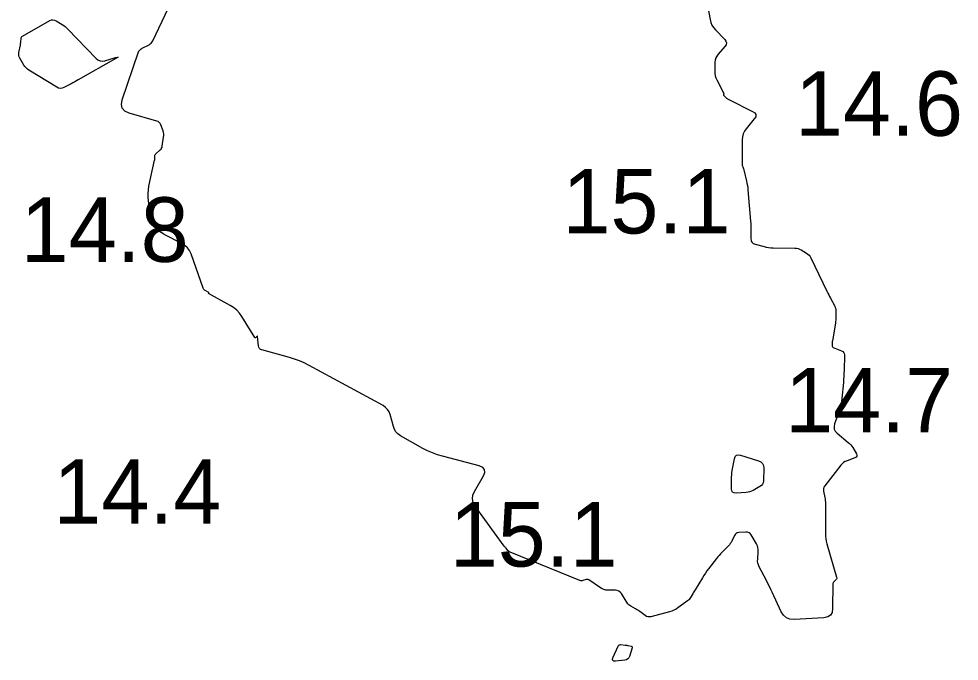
# Model space of a CAD drawing. Extents: x 1023796 to 1112670, y 656573 to 837340.
# Drawn here: x 1101305.4 to 1101378.2, y 688126.7 to 688176.5 of the extents above; entities that cross this region are included whole.
import ezdxf

# ---------------------------------------------------------------- set-up
doc = ezdxf.new("R2010")
doc.units = 0
doc.layers.add('V-CHAN-CONT-15FT', color=7, linetype='Continuous')
doc.layers.add('V-TOPO-SOUN', color=7, linetype='Continuous')

msp = doc.modelspace()

# ---------------------------------------------------------------- linework, layer by layer
at = {"layer": 'V-CHAN-CONT-15FT'}
msp.add_lwpolyline([(1101358.479, 688178.778), (1101358.905, 688176.459), (1101358.963, 688176.235), (1101359.051, 688176.027), (1101359.169, 688175.834), (1101359.318, 688175.657), (1101360.037, 688174.914), (1101360.137, 688174.777), (1101360.172, 688174.638), (1101360.143, 688174.497), (1101360.049, 688174.356), (1101359.524, 688173.764), (1101359.421, 688173.627), (1101359.347, 688173.479), (1101359.3, 688173.319), (1101359.282, 688173.149), (1101359.266, 688172.445), (1101359.272, 688172.271), (1101359.3, 688172.103), (1101359.349, 688171.939), (1101359.42, 688171.781), (1101359.946, 688170.768), (1101359.954, 688170.751), (1101359.959, 688170.733), (1101359.961, 688170.714), (1101359.96, 688170.695), (1101359.953, 688170.618), (1101359.953, 688170.6), (1101359.957, 688170.583), (1101359.965, 688170.568), (1101359.977, 688170.554), (1101360.179, 688170.365), (1101360.218, 688170.33), (1101360.26, 688170.299), (1101360.304, 688170.271), (1101360.35, 688170.247), (1101362.202, 688169.338), (1101362.375, 688169.22), (1101362.454, 688169.082), (1101362.439, 688168.923), (1101362.329, 688168.745), (1101361.704, 688167.991), (1101361.567, 688167.795), (1101361.469, 688167.585), (1101361.411, 688167.362), (1101361.391, 688167.124), (1101361.391, 688165.23), (1101361.392, 688165.202), (1101361.396, 688165.175), (1101361.402, 688165.148), (1101361.411, 688165.122), (1101361.451, 688165.018), (1101361.461, 688164.992), (1101361.47, 688164.966), (1101361.478, 688164.939), (1101361.485, 688164.912), (1101361.726, 688163.937), (1101361.765, 688163.765), (1101361.797, 688163.592), (1101361.823, 688163.418), (1101361.841, 688163.242), (1101362.047, 688160.825), (1101362.06, 688160.656), (1101362.068, 688160.487), (1101362.072, 688160.317), (1101362.073, 688160.148), (1101362.065, 688159.47), (1101362.084, 688159.316), (1101362.144, 688159.194), (1101362.246, 688159.103), (1101362.389, 688159.043), (1101363.089, 688158.855), (1101363.261, 688158.814), (1101363.434, 688158.785), (1101363.609, 688158.766), (1101363.785, 688158.758), (1101365.482, 688158.734), (1101365.606, 688158.724), (1101365.726, 688158.698), (1101365.841, 688158.657), (1101365.951, 688158.599), (1101366.384, 688158.338), (1101366.485, 688158.266), (1101366.573, 688158.183), (1101366.648, 688158.087), (1101366.71, 688157.98), (1101367.96, 688155.391), (1101368.027, 688155.254), (1101368.095, 688155.117), (1101368.165, 688154.981), (1101368.235, 688154.846), (1101368.559, 688154.233), (1101368.604, 688154.133), (1101368.636, 688154.03), (1101368.655, 688153.923), (1101368.66, 688153.813), (1101368.653, 688153.368), (1101368.649, 688153.257), (1101368.641, 688153.146), (1101368.629, 688153.036), (1101368.612, 688152.926), (1101368.379, 688151.541), (1101368.373, 688151.495), (1101368.368, 688151.449), (1101368.365, 688151.403), (1101368.364, 688151.356), (1101368.364, 688151.171), (1101368.369, 688151.128), (1101368.385, 688151.092), (1101368.412, 688151.063), (1101368.449, 688151.041), (1101369.091, 688150.769), (1101369.197, 688150.707), (1101369.271, 688150.626), (1101369.314, 688150.524), (1101369.326, 688150.403), (1101369.289, 688149.262), (1101369.28, 688149.028), (1101369.267, 688148.794), (1101369.25, 688148.561), (1101369.23, 688148.328), (1101369.113, 688147.066), (1101369.082, 688146.818), (1101369.036, 688146.573), (1101368.975, 688146.331), (1101368.899, 688146.092), (1101368.551, 688145.105), (1101368.506, 688144.897), (1101368.525, 688144.707), (1101368.607, 688144.534), (1101368.752, 688144.379), (1101369.604, 688143.676), (1101369.705, 688143.584), (1101369.798, 688143.485), (1101369.881, 688143.379), (1101369.956, 688143.265), (1101370.239, 688142.793), (1101370.284, 688142.685), (1101370.28, 688142.594), (1101370.226, 688142.52), (1101370.121, 688142.465), (1101369.514, 688142.248), (1101369.376, 688142.188), (1101369.251, 688142.111), (1101369.138, 688142.016), (1101369.038, 688141.904), (1101367.792, 688140.305), (1101367.73, 688140.207), (1101367.693, 688140.103), (1101367.681, 688139.994), (1101367.694, 688139.879), (1101367.794, 688139.407), (1101367.816, 688139.288), (1101367.832, 688139.169), (1101367.842, 688139.05), (1101367.847, 688138.929), (1101367.856, 688138.158), (1101367.858, 688137.989), (1101367.859, 688137.821), (1101367.858, 688137.652), (1101367.857, 688137.483), (1101367.847, 688136.607), (1101367.853, 688136.405), (1101367.873, 688136.206), (1101367.907, 688136.009), (1101367.956, 688135.813), (1101368.71, 688133.225), (1101368.719, 688133.173), (1101368.714, 688133.123), (1101368.695, 688133.077), (1101368.661, 688133.035), (1101368.5, 688132.874), (1101368.465, 688132.831), (1101368.44, 688132.785), (1101368.424, 688132.734), (1101368.419, 688132.679), (1101368.401, 688130.787), (1101368.356, 688130.492), (1101368.229, 688130.276), (1101368.019, 688130.138), (1101367.727, 688130.078), (1101365.427, 688129.939), (1101365.094, 688129.961), (1101364.813, 688130.07), (1101364.584, 688130.266), (1101364.408, 688130.549), (1101363.716, 688132.051), (1101363.609, 688132.28), (1101363.499, 688132.507), (1101363.386, 688132.734), (1101363.271, 688132.958), (1101362.712, 688134.031), (1101362.651, 688134.17), (1101362.611, 688134.312), (1101362.592, 688134.459), (1101362.593, 688134.611), (1101362.638, 688135.224), (1101362.638, 688135.375), (1101362.616, 688135.52), (1101362.572, 688135.661), (1101362.505, 688135.796), (1101362.089, 688136.502), (1101362.013, 688136.602), (1101361.921, 688136.67), (1101361.813, 688136.708), (1101361.688, 688136.715), (1101361.125, 688136.679), (1101361.016, 688136.659), (1101360.923, 688136.615), (1101360.848, 688136.545), (1101360.789, 688136.452), (1101360.588, 688136.027), (1101360.533, 688135.923), (1101360.471, 688135.826), (1101360.401, 688135.733), (1101360.322, 688135.647), (1101359.824, 688135.143), (1101359.715, 688135.029), (1101359.61, 688134.913), (1101359.508, 688134.793), (1101359.41, 688134.671), (1101358.795, 688133.88), (1101358.667, 688133.71), (1101358.544, 688133.537), (1101358.426, 688133.361), (1101358.313, 688133.181), (1101357.74, 688132.24), (1101357.695, 688132.165), (1101357.65, 688132.091), (1101357.606, 688132.016), (1101357.561, 688131.941), (1101357.384, 688131.641), (1101357.337, 688131.569), (1101357.283, 688131.503), (1101357.223, 688131.442), (1101357.156, 688131.387), (1101356.417, 688130.839), (1101356.267, 688130.738), (1101356.109, 688130.653), (1101355.944, 688130.584), (1101355.771, 688130.532), (1101354.313, 688130.161), (1101354.198, 688130.144), (1101354.089, 688130.152), (1101353.984, 688130.186), (1101353.885, 688130.246), (1101353.466, 688130.557), (1101353.383, 688130.616), (1101353.299, 688130.672), (1101353.212, 688130.726), (1101353.124, 688130.776), (1101352.766, 688130.972), (1101352.681, 688131.026), (1101352.605, 688131.089), (1101352.538, 688131.161), (1101352.479, 688131.243), (1101352.034, 688131.957), (1101351.945, 688132.068), (1101351.839, 688132.148), (1101351.716, 688132.196), (1101351.574, 688132.212), (1101350.974, 688132.213), (1101350.827, 688132.224), (1101350.687, 688132.256), (1101350.554, 688132.31), (1101350.427, 688132.385), (1101349.517, 688133.013), (1101349.465, 688133.041), (1101349.41, 688133.056), (1101349.354, 688133.056), (1101349.296, 688133.041), (1101349.06, 688132.956), (1101349.001, 688132.941), (1101348.943, 688132.936), (1101348.884, 688132.943), (1101348.826, 688132.961), (1101343.426, 688135.172), (1101343.376, 688135.196), (1101343.33, 688135.225), (1101343.287, 688135.258), (1101343.248, 688135.297), (1101343.099, 688135.462), (1101343.062, 688135.504), (1101343.026, 688135.547), (1101342.992, 688135.59), (1101342.958, 688135.635), (1101340.712, 688138.719), (1101340.556, 688139.002), (1101340.494, 688139.289), (1101340.525, 688139.581), (1101340.651, 688139.878), (1101341.343, 688141.076), (1101341.453, 688141.349), (1101341.435, 688141.569), (1101341.291, 688141.736), (1101341.02, 688141.851), (1101338.18, 688142.593), (1101337.784, 688142.71), (1101337.399, 688142.852), (1101337.024, 688143.018), (1101336.659, 688143.209), (1101334.918, 688144.191), (1101334.726, 688144.324), (1101334.572, 688144.485), (1101334.455, 688144.675), (1101334.374, 688144.893), (1101334.126, 688145.825), (1101334.046, 688146.043), (1101333.928, 688146.231), (1101333.772, 688146.391), (1101333.579, 688146.521), (1101327.836, 688149.645), (1101327.47, 688149.831), (1101327.096, 688149.994), (1101326.712, 688150.136), (1101326.319, 688150.255), (1101324.187, 688150.836), (1101324.076, 688150.882), (1101323.994, 688150.952), (1101323.941, 688151.045), (1101323.916, 688151.162), (1101323.856, 688151.87), (1101323.851, 688151.895), (1101323.841, 688151.907), (1101323.826, 688151.904), (1101323.805, 688151.888), (1101323.715, 688151.798), (1101323.693, 688151.781), (1101323.672, 688151.777), (1101323.653, 688151.786), (1101323.635, 688151.807), (1101322.632, 688153.43), (1101322.449, 688153.69), (1101322.236, 688153.919), (1101321.996, 688154.119), (1101321.727, 688154.289), (1101320.045, 688155.208), (1101320.038, 688155.213), (1101320.035, 688155.219), (1101320.036, 688155.226), (1101320.042, 688155.233), (1101320.071, 688155.262), (1101320.077, 688155.269), (1101320.078, 688155.276), (1101320.075, 688155.282), (1101320.068, 688155.287), (1101319.781, 688155.454), (1101319.734, 688155.487), (1101319.695, 688155.526), (1101319.664, 688155.572), (1101319.64, 688155.624), (1101318.704, 688158.28), (1101318.586, 688158.538), (1101318.427, 688158.761), (1101318.228, 688158.948), (1101317.989, 688159.099), (1101316.625, 688159.801), (1101316.528, 688159.854), (1101316.434, 688159.912), (1101316.343, 688159.974), (1101316.255, 688160.041), (1101315.784, 688160.421), (1101315.762, 688160.44), (1101315.743, 688160.461), (1101315.727, 688160.485), (1101315.714, 688160.51), (1101315.665, 688160.616), (1101315.653, 688160.643), (1101315.644, 688160.67), (1101315.637, 688160.698), (1101315.632, 688160.727), (1101315.398, 688162.388), (1101315.37, 688162.674), (1101315.368, 688162.959), (1101315.39, 688163.243), (1101315.439, 688163.526), (1101315.873, 688165.542), (1101315.881, 688165.587), (1101315.888, 688165.632), (1101315.892, 688165.677), (1101315.894, 688165.722), (1101315.899, 688165.903), (1101315.904, 688165.947), (1101315.918, 688165.986), (1101315.939, 688166.022), (1101315.969, 688166.054), (1101316.31, 688166.352), (1101316.371, 688166.415), (1101316.418, 688166.486), (1101316.452, 688166.565), (1101316.472, 688166.651), (1101316.574, 688167.341), (1101316.585, 688167.462), (1101316.58, 688167.582), (1101316.561, 688167.701), (1101316.526, 688167.818), (1101316.357, 688168.283), (1101316.305, 688168.389), (1101316.234, 688168.474), (1101316.144, 688168.539), (1101316.035, 688168.584), (1101313.895, 688169.206), (1101313.565, 688169.356), (1101313.366, 688169.575), (1101313.3, 688169.863), (1101313.366, 688170.219), (1101314.622, 688173.951), (1101314.635, 688173.982), (1101314.651, 688174.011), (1101314.671, 688174.037), (1101314.694, 688174.061), (1101314.795, 688174.152), (1101314.821, 688174.173), (1101314.848, 688174.193), (1101314.876, 688174.212), (1101314.906, 688174.228), (1101315.445, 688174.507), (1101315.539, 688174.565), (1101315.619, 688174.635), (1101315.687, 688174.718), (1101315.742, 688174.813), (1101316.938, 688177.304)], dxfattribs=at)
for points in [[(1101308.944, 688175.906), (1101309.049, 688175.816), (1101309.149, 688175.718), (1101311.335, 688173.446), (1101311.488, 688173.321), (1101311.655, 688173.249), (1101311.835, 688173.231), (1101312.03, 688173.265), (1101312.835, 688173.51), (1101312.988, 688173.551), (1101313.045, 688173.55), (1101313.006, 688173.508), (1101312.871, 688173.425), (1101309.96, 688171.777), (1101309.821, 688171.7), (1101309.683, 688171.623), (1101309.543, 688171.548), (1101309.403, 688171.474), (1101308.842, 688171.18), (1101308.703, 688171.126), (1101308.565, 688171.111), (1101308.428, 688171.136), (1101308.293, 688171.2), (1101306.135, 688172.536), (1101306.021, 688172.617), (1101305.919, 688172.709), (1101305.83, 688172.813), (1101305.752, 688172.928), (1101305.445, 688173.451), (1101305.394, 688173.556), (1101305.364, 688173.665), (1101305.355, 688173.778), (1101305.366, 688173.894), (1101305.473, 688174.48), (1101305.483, 688174.542), (1101305.493, 688174.604), (1101305.5, 688174.667), (1101305.507, 688174.73), (1101305.53, 688174.981), (1101305.541, 688175.039), (1101305.566, 688175.09), (1101305.602, 688175.133), (1101305.65, 688175.168), (1101307.759, 688176.371), (1101307.881, 688176.423), (1101308.001, 688176.438), (1101308.121, 688176.418), (1101308.241, 688176.362), (1101308.717, 688176.067), (1101308.833, 688175.99)], [(1101360.941, 688142.683), (1101361.082, 688142.721), (1101361.263, 688142.691), (1101362.662, 688142.246), (1101362.841, 688142.162), (1101362.967, 688142.04), (1101363.041, 688141.881), (1101363.062, 688141.684), (1101363.036, 688140.688), (1101363.017, 688140.549), (1101362.966, 688140.429), (1101362.884, 688140.328), (1101362.771, 688140.245), (1101362.255, 688139.954), (1101362.124, 688139.889), (1101361.987, 688139.839), (1101361.847, 688139.806), (1101361.701, 688139.789), (1101360.922, 688139.739), (1101360.766, 688139.751), (1101360.654, 688139.811), (1101360.587, 688139.919), (1101360.565, 688140.074), (1101360.565, 688140.79), (1101360.568, 688140.969), (1101360.58, 688141.147), (1101360.6, 688141.324), (1101360.627, 688141.501), (1101360.785, 688142.402), (1101360.843, 688142.576)], [(1101352.528, 688126.881), (1101352.43, 688126.824), (1101352.308, 688126.794), (1101351.579, 688126.709), (1101351.442, 688126.711), (1101351.364, 688126.756), (1101351.344, 688126.844), (1101351.382, 688126.976), (1101351.777, 688127.868), (1101351.814, 688127.928), (1101351.861, 688127.969), (1101351.92, 688127.99), (1101351.991, 688127.992), (1101352.33, 688127.956), (1101352.388, 688127.949), (1101352.445, 688127.941), (1101352.503, 688127.931), (1101352.56, 688127.92), (1101352.787, 688127.873), (1101352.835, 688127.855), (1101352.864, 688127.827), (1101352.874, 688127.788), (1101352.866, 688127.738), (1101352.656, 688127.081), (1101352.604, 688126.967)]]:
    msp.add_lwpolyline(points, close=True, dxfattribs=at)

# ---------------------------------------------------------------- texts
at = {"layer": 'V-TOPO-SOUN'}
for s, p in [('14.6 ', (1101365.484, 688167.44)), ('15.1 ', (1101347.467, 688159.87)), ('14.8 ', (1101305.502, 688157.67)), ('14.7 ', (1101364.722, 688144.45)), ('14.4 ', (1101308.032, 688137.36)), ('15.1 ', (1101338.737, 688134.05))]:
    msp.add_text(s, height=5, dxfattribs=at).set_placement(p)

doc.saveas('drawing.dxf')
